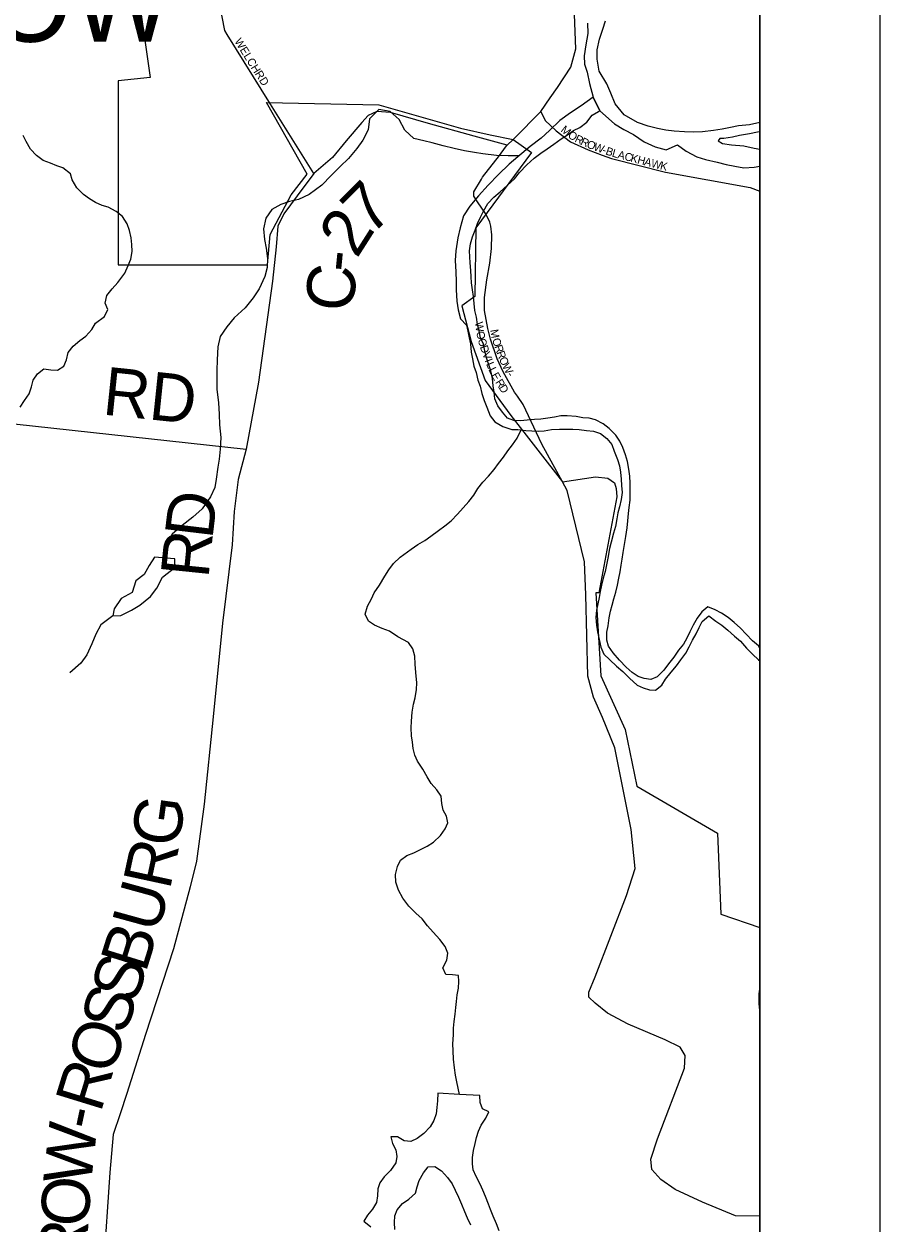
# Model space of a CAD drawing. Extents: x 0 to 34, y -4 to 22.
# Drawn here: x 8.287 to 9, y 15.668 to 16.667 of the extents above; entities that cross this region are included whole.
import ezdxf

# ---------------------------------------------------------------- set-up
doc = ezdxf.new("R2010")
doc.units = 0
for name, color, linetype in [('GM_X_City_Street', 7, 'Continuous'), ('GM_X_City_Street_Text', 7, 'Continuous'), ('GM_X_Corporation', 7, 'Continuous'), ('GM_X_Corporation_Text', 7, 'Continuous'), ('GM_X_County_Road', 7, 'Continuous'), ('GM_X_County_Road_Text', 7, 'Continuous'), ('GM_X_County_ROW', 7, 'Continuous'), ('GM_X_Major_River', 7, 'Continuous'), ('GM_X_Minor_Lake', 7, 'Continuous'), ('GM_X_Minor_River', 7, 'Continuous'), ('GM_X_Township', 7, 'Continuous'), ('GM_X_Township_Road', 7, 'Continuous'), ('GM_X_Township_Road_Text', 7, 'Continuous'), ('SH_Data', 7, 'Continuous'), ('SN_P_Text', 7, 'Continuous')]:
    doc.layers.add(name, color=color, linetype=linetype)

msp = doc.modelspace()

# ---------------------------------------------------------------- linework, layer by layer
at = {"layer": 'GM_X_City_Street'}
for points in [[(8.45661, 16.6587), (8.45445, 16.66217), (8.45001, 16.68493), (8.44697, 16.70815), (8.44392, 16.72884), (8.43897, 16.77442), (8.43894, 16.78418), (8.44325, 16.8022), (8.44661, 16.82062), (8.45267, 16.8352), (8.45638, 16.8567), (8.46053, 16.88077), (8.465, 16.89151), (8.47232, 16.89667), (8.4838, 16.89684), (8.49129, 16.89967)], [(8.49265, 16.6008), (8.45661, 16.6587)], [(8.69532, 16.57202), (8.71752, 16.5947), (8.72549, 16.60607)], [(8.71752, 16.5947), (8.72132, 16.58711), (8.73034, 16.57837), (8.74234, 16.56943), (8.757, 16.56266), (8.76881, 16.55833)], [(8.76881, 16.55833), (8.7766, 16.55548), (8.8213, 16.54405), (8.89193, 16.53122), (8.9, 16.52824)], [(8.6981, 16.35758), (8.69572, 16.36094), (8.68618, 16.37769), (8.6812, 16.3887), (8.67564, 16.40513), (8.67347, 16.41393), (8.67065, 16.42882), (8.67082, 16.43984), (8.67257, 16.45457), (8.67522, 16.46833), (8.67649, 16.48063), (8.67686, 16.49197), (8.67612, 16.49923), (8.67506, 16.50257), (8.672, 16.50881), (8.66488, 16.51938)]]:
    msp.add_lwpolyline(points, dxfattribs=at)
at = {"layer": 'GM_X_Corporation'}
msp.add_lwpolyline([(8.36391, 16.8226), (8.39233, 16.62295), (8.36586, 16.62013), (8.36585, 16.46681), (8.49016, 16.46694), (8.4923, 16.49217), (8.5098, 16.52526), (8.52318, 16.54236), (8.48922, 16.60209), (8.5828, 16.60017), (8.65073, 16.58064), (8.67544, 16.57505), (8.69467, 16.57136), (8.70995, 16.56041), (8.66344, 16.49761), (8.6628, 16.44042), (8.652, 16.43282), (8.65952, 16.40295), (8.67119, 16.37064), (8.69258, 16.34138), (8.73566, 16.28634), (8.76324, 16.2905), (8.77344, 16.28921), (8.77886, 16.28552), (8.78034, 16.28059), (8.78089, 16.27374), (8.76598, 16.19374), (8.76347, 16.19374), (8.76747, 16.12458), (8.78773, 16.07989), (8.79757, 16.03293), (8.8646, 15.99354), (8.86763, 15.92613), (8.9, 15.91505), (8.9, 17.17268)], dxfattribs=at)
at = {"layer": 'GM_X_County_Road'}
for points in [[(8.68948, 16.56665), (8.66228, 16.57418), (8.62412, 16.58452), (8.59262, 16.59372), (8.58099, 16.59462), (8.57387, 16.59118), (8.56854, 16.58551), (8.55567, 16.57006), (8.5441, 16.55624), (8.5287, 16.54291), (8.51468, 16.52451), (8.50365, 16.50932), (8.49878, 16.49926), (8.4973, 16.48181), (8.49426, 16.45346), (8.48252, 16.36936), (8.4724, 16.31339), (8.46571, 16.28815), (8.46227, 16.26154), (8.4607, 16.23373), (8.45252, 16.16867), (8.44489, 16.0905), (8.43744, 16.01792), (8.4309, 15.97024), (8.42582, 15.94909), (8.41172, 15.89749), (8.38861, 15.82615), (8.37296, 15.77693), (8.36738, 15.75987), (8.36161, 15.74287), (8.35882, 15.71098), (8.35368, 15.63328)], [(8.66811, 16.53813), (8.66918, 16.53992), (8.68315, 16.55791), (8.68816, 16.56484), (8.68948, 16.56665), (8.69467, 16.57136), (8.69532, 16.57202)], [(8.66488, 16.51938), (8.66343, 16.52153), (8.66188, 16.52405), (8.66179, 16.52763), (8.66811, 16.53813)], [(8.9, 15.67471), (8.87957, 15.675), (8.8523, 15.68649), (8.82956, 15.69709), (8.81745, 15.70535), (8.81014, 15.71351), (8.80924, 15.72208), (8.81465, 15.73908), (8.83717, 15.79798), (8.83792, 15.80866), (8.83352, 15.81543), (8.8211, 15.82155), (8.7904, 15.83472), (8.77323, 15.84388), (8.76298, 15.8521), (8.75774, 15.85701), (8.75756, 15.86129), (8.76289, 15.87402), (8.78906, 15.94166), (8.79619, 15.96424), (8.79283, 15.99665), (8.77924, 16.06481), (8.76907, 16.08987), (8.7614, 16.10686), (8.75668, 16.12433), (8.7551, 16.19225), (8.75405, 16.21953), (8.7397, 16.27903), (8.73566, 16.28634), (8.71839, 16.31758), (8.70298, 16.35069), (8.6981, 16.35758)]]:
    msp.add_lwpolyline(points, dxfattribs=at)
at = {"layer": 'GM_X_County_ROW'}
msp.add_lwpolyline([(8.72549, 16.60607), (8.73149, 16.61464), (8.74254, 16.63166), (8.74682, 16.64674), (8.74471, 16.69729), (8.74316, 16.73269), (8.74034, 16.78248), (8.73836, 16.80364), (8.72637, 16.82677), (8.72427, 16.83271)], dxfattribs=at)
at = {"layer": 'GM_X_Major_River'}
msp.add_line((8.76114, 16.60664), (8.76681, 16.59515), dxfattribs=at)
for points in [[(8.75647, 16.66803), (8.75678, 16.65947), (8.7552, 16.65015), (8.75363, 16.64084), (8.75399, 16.63415), (8.75622, 16.62741), (8.75812, 16.61801), (8.76114, 16.60664)], [(8.9, 16.58549), (8.89132, 16.5834), (8.8822, 16.58256), (8.87548, 16.58139), (8.86848, 16.57996), (8.86149, 16.5788), (8.85237, 16.57769), (8.84433, 16.57736), (8.83711, 16.57754), (8.82856, 16.57829), (8.82162, 16.579), (8.8147, 16.58051), (8.80699, 16.5823), (8.79823, 16.58546), (8.78689, 16.59189), (8.77963, 16.6009), (8.77584, 16.60981), (8.77257, 16.61765), (8.76615, 16.62823), (8.76453, 16.63816), (8.76446, 16.64591), (8.76657, 16.65495), (8.76919, 16.66317), (8.77151, 16.67006)], [(8.76681, 16.59515), (8.77893, 16.58434), (8.78684, 16.5796), (8.79476, 16.57539), (8.8037, 16.56929), (8.8127, 16.56505), (8.822, 16.56268), (8.83147, 16.56672), (8.83857, 16.56147), (8.84755, 16.55696), (8.85472, 16.55465), (8.86456, 16.55253), (8.87201, 16.55047), (8.87919, 16.54896), (8.88665, 16.5477), (8.89523, 16.54829), (8.9, 16.54904)], [(8.9, 16.57777), (8.89813, 16.57735), (8.8914, 16.57592), (8.88307, 16.57452), (8.87715, 16.57333), (8.86989, 16.57218), (8.86667, 16.57199), (8.86529, 16.57015), (8.86898, 16.56792), (8.87645, 16.56694), (8.88659, 16.56588), (8.89537, 16.56406), (8.9, 16.56331)]]:
    msp.add_lwpolyline(points, dxfattribs=at)
at = {"layer": 'GM_X_Minor_Lake'}
for points in [[(8.36249, 16.18046), (8.36126, 16.17461), (8.36796, 16.17498), (8.37691, 16.1793), (8.3837, 16.1834), (8.39272, 16.19066), (8.39799, 16.19775), (8.40277, 16.20671), (8.41289, 16.21502), (8.41308, 16.22223), (8.40559, 16.22268)], [(8.40559, 16.22268), (8.39598, 16.22346), (8.39152, 16.21662), (8.38731, 16.20897), (8.38048, 16.2038), (8.37755, 16.19398), (8.36833, 16.18913), (8.36249, 16.18046)], [(8.63201, 15.77712), (8.63163, 15.7707), (8.631, 15.7651), (8.63038, 15.76003), (8.62869, 15.75445), (8.62539, 15.74915), (8.62021, 15.74362), (8.61479, 15.73943), (8.6094, 15.73684), (8.60379, 15.73747), (8.59823, 15.74076), (8.59288, 15.74085), (8.59413, 15.73521), (8.59698, 15.73009), (8.59769, 15.72446), (8.5968, 15.71913), (8.59241, 15.71278), (8.58724, 15.70752), (8.58368, 15.7025), (8.58199, 15.69744), (8.58163, 15.69157), (8.58073, 15.68624), (8.57743, 15.68068), (8.57334, 15.67566), (8.57031, 15.67063), (8.57611, 15.66573)], [(8.64997, 15.77614), (8.63201, 15.77712)], [(8.67411, 15.68477), (8.6715, 15.69121), (8.66944, 15.69632), (8.66712, 15.70143), (8.66375, 15.70764), (8.66143, 15.71329), (8.66072, 15.71838), (8.66081, 15.72372), (8.6617, 15.72932), (8.66287, 15.73519), (8.66402, 15.74025), (8.66572, 15.74557), (8.66794, 15.75061), (8.67178, 15.75643), (8.67428, 15.76174), (8.66897, 15.76423), (8.66718, 15.76934), (8.66675, 15.77522), (8.64997, 15.77614)], [(8.59614, 15.66354), (8.5957, 15.66942), (8.59606, 15.67503), (8.59802, 15.68008), (8.60239, 15.68536), (8.6078, 15.68901), (8.61323, 15.69401), (8.61465, 15.69906), (8.61635, 15.70438), (8.61993, 15.71074), (8.62376, 15.71576), (8.62938, 15.71621), (8.63494, 15.71237), (8.63993, 15.70695), (8.64385, 15.7018), (8.64644, 15.69642), (8.64901, 15.69049), (8.6516, 15.68484), (8.65417, 15.67865), (8.65622, 15.67327), (8.65906, 15.66761)], [(8.68305, 15.66242), (8.68074, 15.66834), (8.67791, 15.6748), (8.67586, 15.68018), (8.67411, 15.68477)]]:
    msp.add_lwpolyline(points, dxfattribs=at)
at = {"layer": 'GM_X_Minor_River'}
for p, q in [((8.76681, 16.59515), (8.76114, 16.60664)), ((8.9, 16.14785), (8.89878, 16.1498)), ((8.89885, 16.13804), (8.9, 16.13728))]:
    msp.add_line(p, q, dxfattribs=at)
for points in [[(8.76114, 16.60664), (8.75121, 16.5992), (8.74223, 16.59355), (8.7335, 16.58708), (8.72472, 16.57875), (8.71787, 16.5725), (8.70886, 16.56551), (8.69847, 16.55695), (8.69135, 16.55072), (8.68229, 16.54212), (8.67376, 16.53325), (8.66577, 16.52436), (8.65859, 16.51572), (8.6533, 16.50783), (8.65037, 16.49775), (8.64855, 16.48951), (8.64693, 16.47859), (8.64645, 16.47058), (8.64701, 16.46121), (8.64707, 16.45293), (8.64716, 16.44598), (8.64772, 16.43661), (8.64887, 16.42936), (8.65082, 16.42183), (8.65584, 16.41673)], [(8.69847, 16.55695), (8.69929, 16.55773), (8.69045, 16.55769), (8.68083, 16.55793), (8.66935, 16.55928), (8.66243, 16.56053), (8.65416, 16.5618), (8.64538, 16.56389), (8.63633, 16.56599), (8.6273, 16.56862), (8.62011, 16.57014), (8.61187, 16.57222), (8.60455, 16.57908), (8.5997, 16.58802), (8.59211, 16.59463), (8.58278, 16.5962), (8.57509, 16.58837), (8.57378, 16.57932), (8.56954, 16.5706), (8.56455, 16.56378), (8.55764, 16.5554), (8.55051, 16.54889), (8.54309, 16.54133), (8.53539, 16.53324), (8.52475, 16.52548), (8.51581, 16.52143), (8.50827, 16.51975), (8.50125, 16.51725), (8.49364, 16.5129), (8.48864, 16.5058), (8.48681, 16.49703), (8.48765, 16.48792), (8.48907, 16.48067), (8.49018, 16.47209), (8.48972, 16.46461), (8.48792, 16.45717), (8.48311, 16.44687), (8.4781, 16.43951), (8.47146, 16.43112), (8.46241, 16.4228), (8.45633, 16.4152), (8.45077, 16.40732), (8.44867, 16.39855), (8.44813, 16.38787), (8.4479, 16.37906), (8.44794, 16.37024), (8.44803, 16.36328), (8.44935, 16.35202), (8.44991, 16.34266), (8.45021, 16.33383), (8.45128, 16.32311), (8.45076, 16.3135), (8.44975, 16.30524), (8.44876, 16.29831), (8.44744, 16.28846), (8.44619, 16.28154), (8.44277, 16.27361), (8.43556, 16.26363), (8.42789, 16.25687), (8.41914, 16.24987), (8.41066, 16.2426), (8.40614, 16.23336), (8.40559, 16.22268)], [(8.79131, 16.26486), (8.79195, 16.271), (8.79207, 16.27822), (8.79192, 16.28517), (8.79175, 16.29105), (8.79078, 16.29668), (8.78982, 16.30311), (8.78804, 16.30876), (8.786, 16.31494), (8.78341, 16.32006), (8.78002, 16.32519), (8.7745, 16.33063), (8.76948, 16.33445), (8.76311, 16.33776), (8.75779, 16.33918), (8.75271, 16.33953), (8.74711, 16.34069), (8.73963, 16.34107), (8.73428, 16.34116), (8.72892, 16.34017), (8.72355, 16.33919), (8.71765, 16.33848), (8.7123, 16.33803), (8.70614, 16.3376), (8.70078, 16.33715), (8.69516, 16.33724), (8.68985, 16.33919), (8.68565, 16.34434), (8.68173, 16.34948), (8.67942, 16.3554), (8.67871, 16.36102), (8.67799, 16.36612), (8.67729, 16.37228), (8.67607, 16.37871), (8.67402, 16.38436), (8.6725, 16.38946), (8.671, 16.39536), (8.67002, 16.40099), (8.66743, 16.40612), (8.66619, 16.41202), (8.66495, 16.41738), (8.66398, 16.42328), (8.66273, 16.42891), (8.66203, 16.43481), (8.66159, 16.44043), (8.66088, 16.44605), (8.65991, 16.45195), (8.65973, 16.45703), (8.65928, 16.46212), (8.65885, 16.46854), (8.65867, 16.47362), (8.65822, 16.47871), (8.65912, 16.48431), (8.66082, 16.49016), (8.66305, 16.49574), (8.66502, 16.50132), (8.66752, 16.50663), (8.67001, 16.51167), (8.67359, 16.51803), (8.6785, 16.5233), (8.68392, 16.52775), (8.68963, 16.53301), (8.6956, 16.53853), (8.69997, 16.5438), (8.70596, 16.55012), (8.71221, 16.55564), (8.71763, 16.55983), (8.72304, 16.56349), (8.72845, 16.56741), (8.73468, 16.57186), (8.73982, 16.57525), (8.74497, 16.57891), (8.75009, 16.58123), (8.75605, 16.58568), (8.76042, 16.59149), (8.76556, 16.59462), (8.76681, 16.59515)], [(8.28422, 16.34834), (8.28779, 16.35389), (8.29163, 16.35944), (8.2936, 16.36529), (8.29503, 16.37088), (8.2986, 16.37618), (8.30402, 16.38037), (8.30962, 16.37948), (8.31523, 16.37912), (8.32064, 16.38251), (8.32287, 16.38782), (8.32404, 16.39395), (8.32841, 16.39922), (8.33384, 16.40395), (8.33898, 16.40761), (8.34389, 16.41315), (8.34692, 16.41844), (8.3545, 16.42394), (8.35728, 16.42977), (8.35495, 16.43489), (8.3564, 16.44128), (8.36077, 16.44683), (8.36541, 16.4521), (8.37143, 16.46002), (8.37421, 16.4664), (8.37644, 16.47171), (8.37735, 16.47811), (8.37718, 16.48399), (8.37647, 16.48935), (8.37523, 16.49552), (8.37319, 16.50116), (8.36928, 16.50711), (8.364, 16.51147), (8.35737, 16.51505), (8.35231, 16.51647), (8.34701, 16.51896), (8.34197, 16.52198), (8.33695, 16.52553), (8.33143, 16.53097), (8.32753, 16.53772), (8.32601, 16.54282), (8.31967, 16.54773), (8.31462, 16.54941), (8.3093, 16.55164), (8.30346, 16.55387), (8.29764, 16.55797), (8.29265, 16.56313), (8.28928, 16.5696), (8.28669, 16.57472)], [(8.65584, 16.41673), (8.65682, 16.41163), (8.65807, 16.40626), (8.65906, 16.40117), (8.65974, 16.39421), (8.66072, 16.38858), (8.66196, 16.38268), (8.66374, 16.3773), (8.66524, 16.37086), (8.66702, 16.36576), (8.66853, 16.35985), (8.67057, 16.35394), (8.67261, 16.34829), (8.67544, 16.3413), (8.67936, 16.33615), (8.68599, 16.3323), (8.69343, 16.32978), (8.69851, 16.3297), (8.70519, 16.32906), (8.71027, 16.32871), (8.71534, 16.32836), (8.72043, 16.32881), (8.7266, 16.32978), (8.73329, 16.32995), (8.73864, 16.33013), (8.74426, 16.33004), (8.7496, 16.32969), (8.75575, 16.32905), (8.76162, 16.32842), (8.76721, 16.32646), (8.77249, 16.32237), (8.77668, 16.31722), (8.77873, 16.31184), (8.78155, 16.30485), (8.78307, 16.29948), (8.78405, 16.29438), (8.78449, 16.2885), (8.78493, 16.28314), (8.78537, 16.27725), (8.78447, 16.27165), (8.78303, 16.26553), (8.78188, 16.26047), (8.78099, 16.2554), (8.77981, 16.249), (8.77811, 16.24342), (8.77612, 16.23597), (8.77469, 16.23064), (8.77349, 16.22264), (8.77232, 16.21704), (8.77116, 16.21145), (8.76946, 16.20613), (8.76803, 16.20027), (8.76714, 16.19494), (8.76625, 16.18988), (8.76509, 16.18455), (8.76393, 16.17949), (8.76356, 16.17334), (8.76399, 16.16692), (8.7647, 16.1613), (8.7662, 16.15486), (8.7677, 16.14868), (8.77, 16.14276), (8.77501, 16.13814), (8.78054, 16.13271), (8.78581, 16.12834), (8.79133, 16.12264), (8.79792, 16.11692), (8.80297, 16.1147), (8.80802, 16.11302), (8.8131, 16.11267), (8.81825, 16.11687), (8.82155, 16.12189), (8.82619, 16.1277), (8.83056, 16.13298), (8.83412, 16.138), (8.83823, 16.14355), (8.84126, 16.14885), (8.84403, 16.15442), (8.84706, 16.15971), (8.84955, 16.16502), (8.85205, 16.17006), (8.85747, 16.17452), (8.86328, 16.17015), (8.86831, 16.16686), (8.87332, 16.16277), (8.87885, 16.1576), (8.88387, 16.15351), (8.88885, 16.14782), (8.89385, 16.14266), (8.89885, 16.13804)], [(8.69402, 16.31694), (8.69786, 16.32249), (8.70129, 16.32943)], [(8.64997, 15.77614), (8.64768, 15.78649), (8.6467, 15.79212), (8.64573, 15.79828), (8.64505, 15.80551), (8.64463, 15.81247), (8.64447, 15.81835), (8.64486, 15.82583), (8.64495, 15.83118), (8.64558, 15.83678), (8.64621, 15.84292), (8.64684, 15.84852), (8.64746, 15.85359), (8.64809, 15.85893), (8.64898, 15.86453), (8.64934, 15.87014), (8.64916, 15.87522), (8.64409, 15.87557), (8.63847, 15.87593), (8.63616, 15.88158), (8.63948, 15.88794), (8.64011, 15.89381), (8.63806, 15.89919), (8.63361, 15.90514), (8.6281, 15.91111), (8.62337, 15.91653), (8.61892, 15.92222), (8.61365, 15.92711), (8.60786, 15.93282), (8.60263, 15.93959), (8.59926, 15.94632), (8.59696, 15.95278), (8.59654, 15.9592), (8.59825, 15.96586), (8.60075, 15.97116), (8.60617, 15.97509), (8.61182, 15.9774), (8.61748, 15.97999), (8.62315, 15.98284), (8.62829, 15.98623), (8.63399, 15.99175), (8.6381, 15.9973), (8.64033, 16.00234), (8.63908, 16.00771), (8.63622, 16.01284), (8.63525, 16.01847), (8.63454, 16.02436), (8.63116, 16.02976), (8.62643, 16.03491), (8.62304, 16.04058), (8.61941, 16.04706), (8.61497, 16.05354), (8.61265, 16.05866), (8.61141, 16.06429), (8.61069, 16.06938), (8.60998, 16.07474), (8.60982, 16.08143), (8.60991, 16.08704), (8.61058, 16.09451), (8.61176, 16.10118), (8.61291, 16.10624), (8.6141, 16.11317), (8.61446, 16.11878), (8.61353, 16.12735), (8.61312, 16.13431), (8.61269, 16.141), (8.61119, 16.14717), (8.60753, 16.15231), (8.59852, 16.15726), (8.59164, 16.16192), (8.58553, 16.16415), (8.57916, 16.16693), (8.57413, 16.17021), (8.57129, 16.17614), (8.57327, 16.18279), (8.57658, 16.18889), (8.57881, 16.19393), (8.58346, 16.20028), (8.58787, 16.20769), (8.59116, 16.21298), (8.595, 16.21827), (8.60044, 16.22353), (8.60964, 16.23007), (8.61532, 16.23398), (8.621, 16.23737), (8.62614, 16.24103), (8.63237, 16.24574), (8.63779, 16.24967), (8.64294, 16.25386), (8.64838, 16.25939), (8.65302, 16.26466), (8.65765, 16.26993), (8.66176, 16.27521), (8.66506, 16.28078), (8.66943, 16.28605), (8.67406, 16.29106), (8.6787, 16.2966), (8.68253, 16.30162), (8.68663, 16.3069), (8.69019, 16.31192), (8.69402, 16.31694)], [(8.89878, 16.1498), (8.89377, 16.15389), (8.88851, 16.15932), (8.88378, 16.16448), (8.87851, 16.1691), (8.8735, 16.17319), (8.86794, 16.17676), (8.86264, 16.17978), (8.85679, 16.18202), (8.85165, 16.17809), (8.84781, 16.1728), (8.84451, 16.16697), (8.84174, 16.1614), (8.83924, 16.1561), (8.83648, 16.15106), (8.83238, 16.14605), (8.82827, 16.14023), (8.8239, 16.13469), (8.82007, 16.1294), (8.81436, 16.12388), (8.80924, 16.12155), (8.80363, 16.12245), (8.79858, 16.12413), (8.79355, 16.12742), (8.78855, 16.13204), (8.78303, 16.13774), (8.77778, 16.14371), (8.77386, 16.14939), (8.77261, 16.15448), (8.77272, 16.16117), (8.77361, 16.16623), (8.77452, 16.1729), (8.77569, 16.1785), (8.77711, 16.18355), (8.77854, 16.18888), (8.77997, 16.19447), (8.7814, 16.20006), (8.78257, 16.20592), (8.78373, 16.21125), (8.78462, 16.21685), (8.78524, 16.22192), (8.78613, 16.22725), (8.78732, 16.23392), (8.7885, 16.24058), (8.78943, 16.24805), (8.79006, 16.25365), (8.79069, 16.25979), (8.79131, 16.26486)], [(8.36126, 16.17461), (8.35143, 16.1671), (8.34722, 16.15946), (8.3438, 16.15126), (8.33955, 16.14227), (8.33482, 16.13518), (8.32551, 16.12712)], [(8.9, 15.86562), (8.89947, 15.86194), (8.89915, 15.85981), (8.89911, 15.85794), (8.89905, 15.85553), (8.89927, 15.85365), (8.89922, 15.85178), (8.89941, 15.84856), (8.89963, 15.84669), (8.89984, 15.84454), (8.9, 15.84321)]]:
    msp.add_lwpolyline(points, dxfattribs=at)
at = {"layer": 'GM_X_Township'}
msp.add_lwpolyline([(8.9, 14.99227), (8.9, 19.07101)], dxfattribs=at)
at = {"layer": 'GM_X_Township_Road'}
for points in [[(8.5287, 16.54291), (8.49265, 16.6008)], [(8.14141, 16.34854), (8.23056, 16.33986), (8.4724, 16.31339)]]:
    msp.add_lwpolyline(points, dxfattribs=at)
at = {"layer": 'SH_Data'}
for p, q in [((9, 21), (9, 14)), ((8.9, 20.9), (8.9, 14.1))]:
    msp.add_line(p, q, dxfattribs=at)
at = {"layer": 'SN_P_Text'}
msp.add_lwpolyline([(8.9, 14.1), (8.9, 20.9), (2.1, 20.9), (2.1, 14.1)], close=True, dxfattribs=at)

# ---------------------------------------------------------------- texts
at = {"layer": 'GM_X_City_Street_Text'}
for s, height, rotation, p in [('WELCH', 0.006667, 301.76056, (8.46229, 16.65311)), ('RD', 0.006667, 301.9968, (8.4793, 16.62612)), ('M', 0.00667, 321.1553, (8.73365, 16.57832)), ('O', 0.00667, 325.06329, (8.73953, 16.57361)), ('R', 0.00667, 334.09419, (8.74533, 16.56966)), ('R', 0.00667, 334.50295, (8.75013, 16.56733)), ('O', 0.00667, 337.93268, (8.75529, 16.56489)), ('W', 0.00667, 340.56417, (8.76104, 16.56257)), ('-', 0.00667, 340.63584, (8.76823, 16.56002)), ('B', 0.00667, 340.98214, (8.77104, 16.55904)), ('L', 0.00667, 343.745, (8.77637, 16.55721)), ('A', 0.00667, 345.21079, (8.78106, 16.55585)), ('C', 0.00667, 345.29296, (8.78674, 16.55435)), ('K', 0.00667, 345.28167, (8.79184, 16.553)), ('H', 0.00667, 345.30361, (8.79752, 16.55151)), ('A', 0.00667, 345.2798, (8.80319, 16.55003)), ('W', 0.00667, 345.27869, (8.80887, 16.54854)), ('K', 0.00667, 347.07894, (8.81647, 16.54654)), ('W', 0.00667, 276.50359, (8.66284, 16.41916)), ('O', 0.00667, 281.30635, (8.6638, 16.41098)), ('M', 0.00667, 280.07024, (8.67543, 16.41265)), ('O', 0.00667, 285.37931, (8.66507, 16.40472)), ('D', 0.00667, 289.45323, (8.66678, 16.39857)), ('O', 0.00667, 288.12106, (8.67691, 16.40473)), ('R', 0.00667, 289.75948, (8.6788, 16.39895)), ('V', 0.00667, 289.90898, (8.66876, 16.39299)), ('I', 0.00667, 291.16052, (8.67081, 16.38732)), ('R', 0.00667, 290.33767, (8.68062, 16.39392)), ('O', 0.00667, 293.51883, (8.6826, 16.38859)), ('L', 0.00667, 292.94307, (8.67196, 16.38438)), ('L', 0.00667, 294.62131, (8.67387, 16.37986)), ('E', 0.00667, 299.28045, (8.6761, 16.37506)), ('W', 0.00667, 297.35721, (8.68515, 16.38277)), ('R', 0.00667, 301.84136, (8.67947, 16.36919)), ('-', 0.00667, 302.84447, (8.68901, 16.3754)), ('D', 0.00667, 302.68076, (8.68232, 16.36461))]:
    msp.add_text(s, height=height, rotation=rotation, dxfattribs=at).set_placement(p)
at = {"layer": 'GM_X_Corporation_Text'}
msp.add_text('MORROW', height=0.066667, rotation=0.00001, dxfattribs=at).set_placement((7.98561, 16.6527))
at = {"layer": 'GM_X_County_Road_Text'}
for s, rotation, p in [('7', 45.06623, (8.5762, 16.49049)), ('2', 57.46175, (8.56438, 16.4715)), ('-', 84.3839, (8.56438, 16.4598)), ('C', 83.86453, (8.56083, 16.42674)), ('D', 83.18268, (8.44416, 16.23772)), ('R', 84.21367, (8.44087, 16.20523)), ('G', 82.15486, (8.41624, 15.98109)), ('R', 77.76743, (8.4087, 15.94569)), ('U', 74.60008, (8.39877, 15.90941)), ('B', 72.63728, (8.38855, 15.87662)), ('S', 71.90768, (8.38, 15.85044)), ('S', 71.87536, (8.3716, 15.82477)), ('O', 71.87146, (8.36064, 15.79131)), ('R', 72.92654, (8.35106, 15.76009)), ('-', 77.94449, (8.34786, 15.74492)), ('W', 83.81562, (8.34304, 15.69992)), ('O', 86.35117, (8.34084, 15.66525)), ('R', 86.3553, (8.33875, 15.63247))]:
    msp.add_text(s, height=0.04, rotation=rotation, dxfattribs=at).set_placement(p)
at = {"layer": 'GM_X_Township_Road_Text'}
msp.add_text('RD', height=0.04, rotation=354.04432, dxfattribs=at).set_placement((8.35196, 16.34235))

doc.saveas('drawing.dxf')
